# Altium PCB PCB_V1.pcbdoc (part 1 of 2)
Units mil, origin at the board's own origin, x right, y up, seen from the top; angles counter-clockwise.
Board outline 2047.24 x 3937.01 mil, 2 copper layers (Top Layer, Bottom Layer), stack 62.206 mil thick; 59 components, 45 nets, 231 pads, 209 vias.
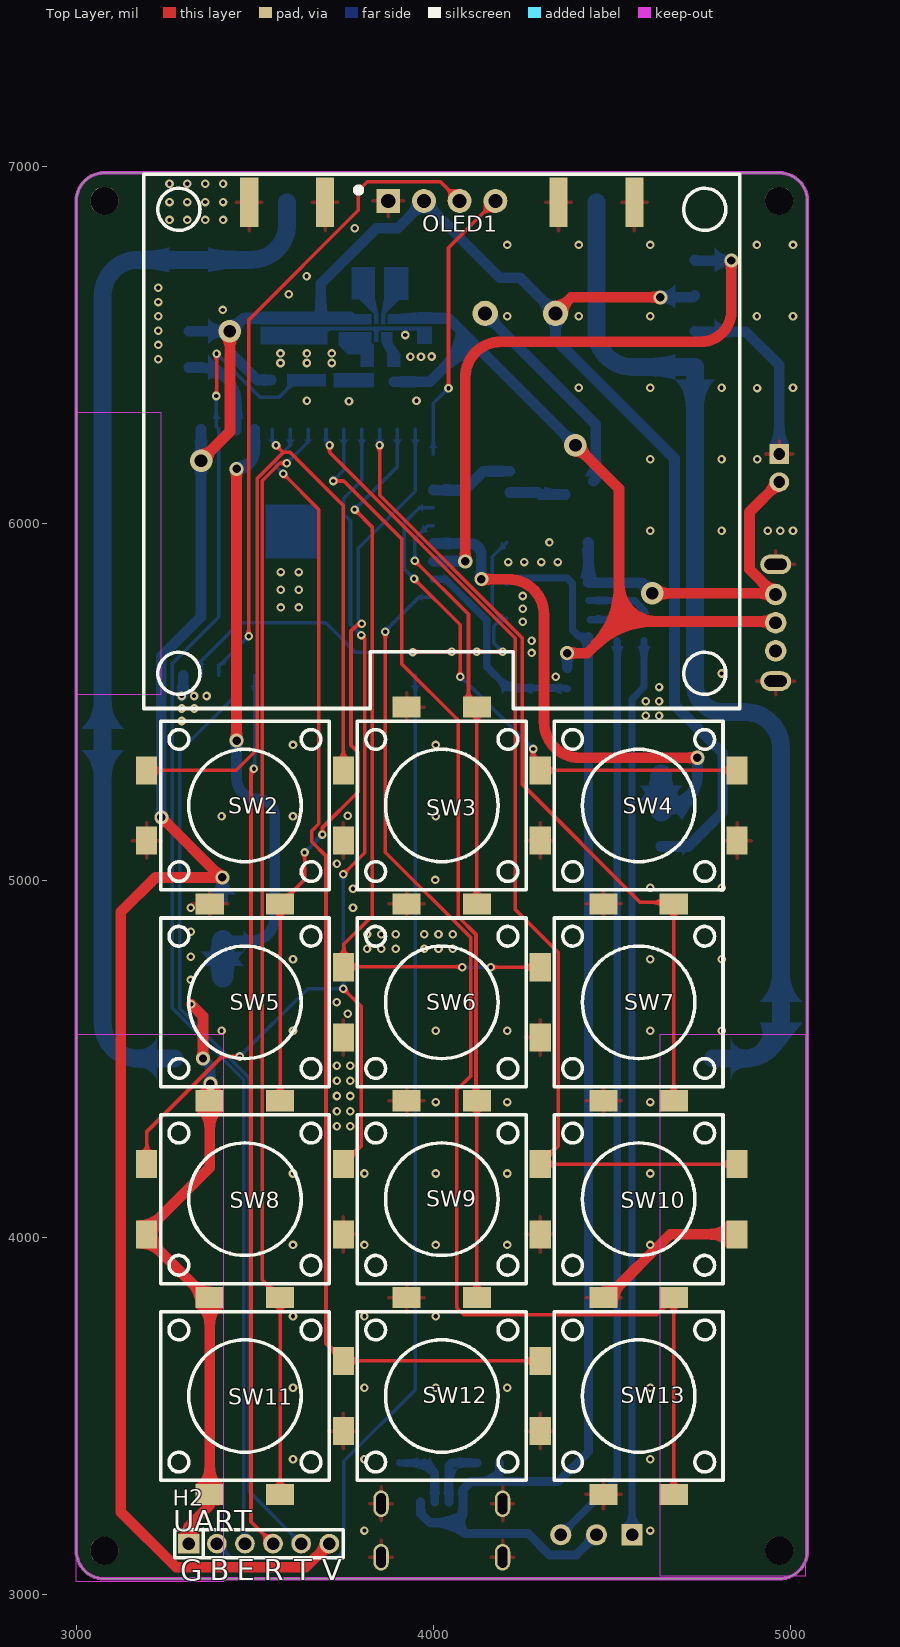
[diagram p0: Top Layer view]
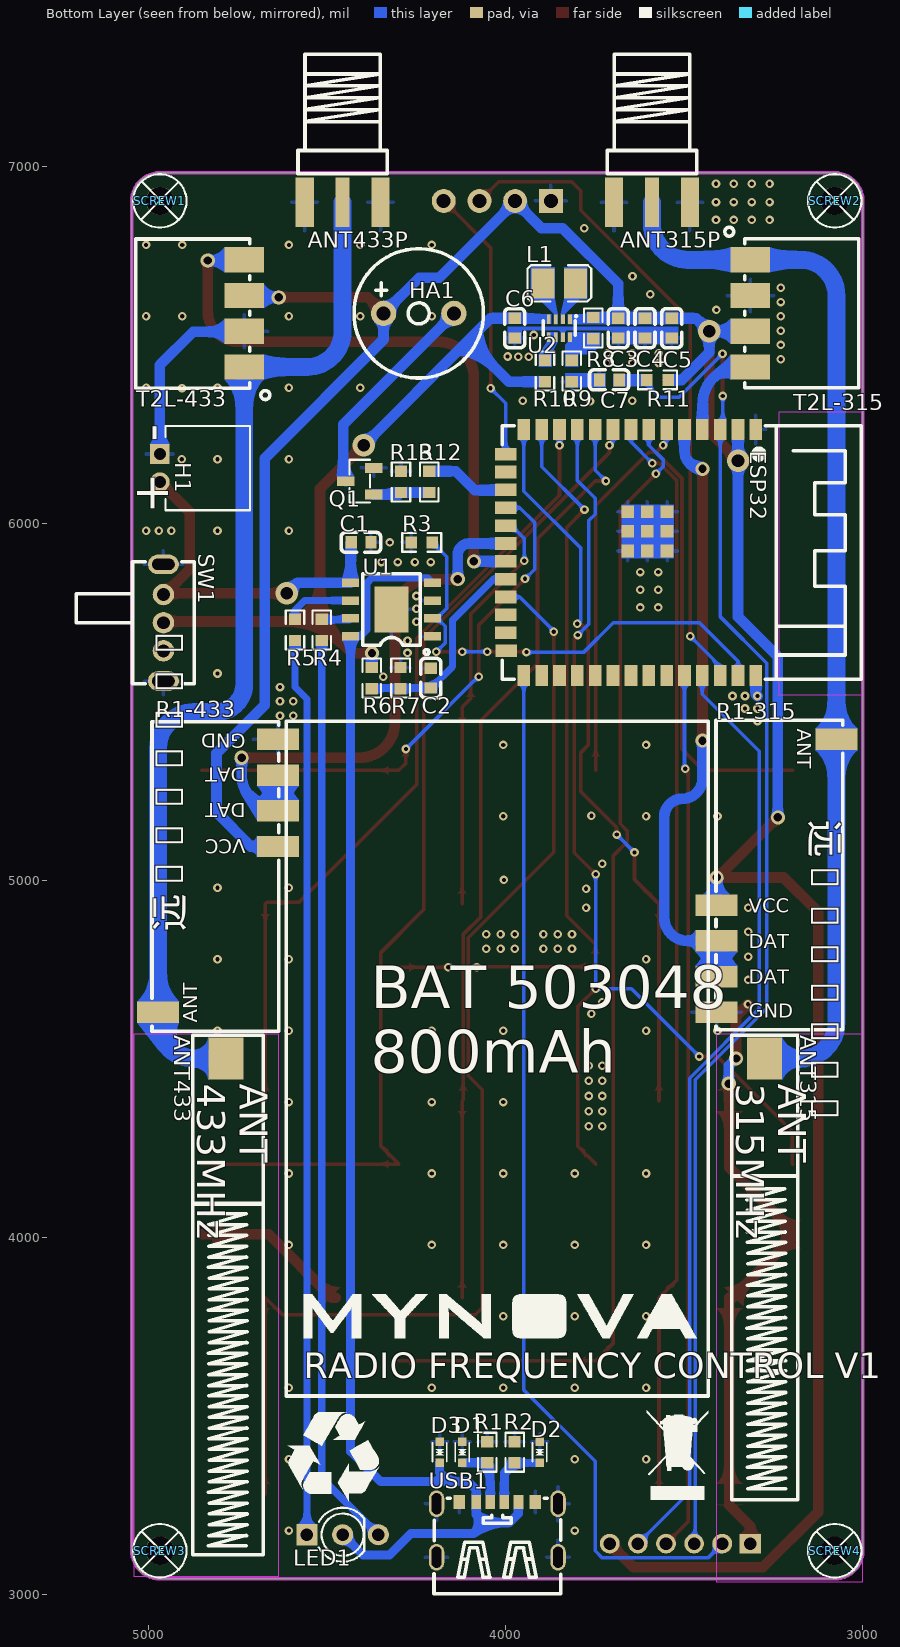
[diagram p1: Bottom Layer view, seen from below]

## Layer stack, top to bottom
Top Solder Mask Layer: solder mask 0.394, Dk 3.3
Top Layer: signal copper 1.379
Dielectric1: surface 59.449, FR4, Dk 4.5
Bottom Layer: signal copper 1.378
Bottom Solder Mask Layer: solder mask 0.394, Dk 3.3

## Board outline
3000,3122.93 ccw(c3078.74,3122.93) 3078.74,3044.19 4968.5,3044.19 ccw(c4968.5,3122.93) 5047.24,3122.93 5047.24,6902.46 ccw(c4968.5,6902.46) 4968.5,6981.2 3078.74,6981.2 ccw(c3078.74,6902.46) 3000,6902.46

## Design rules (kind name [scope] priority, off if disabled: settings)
BoardOutlineClearance copperThickness1oz [All] p0: genericclearance=10 ignorepadtopadclearanceinfootprint=FALSE except(0: Arc-SplitContinuation Track-SplitContinuation SMDPad-SplitContinuation THPad-SplitContinuation Via-SplitContinuation Fill-SplitContinuation Poly-SplitContinuation Region-SplitContinuation Text-SplitContinuation)
BoardOutlineClearance copperThickness2oz [All] p0: genericclearance=10 ignorepadtopadclearanceinfootprint=FALSE except(0: Arc-SplitContinuation Track-SplitContinuation SMDPad-SplitContinuation THPad-SplitContinuation Via-SplitContinuation Fill-SplitContinuation Poly-SplitContinuation Region-SplitContinuation Text-SplitContinuation)
BoardOutlineClearance Plane_innerPlane [All] p0: genericclearance=10 ignorepadtopadclearanceinfootprint=FALSE except(0: Arc-SplitContinuation Track-SplitContinuation SMDPad-SplitContinuation THPad-SplitContinuation Via-SplitContinuation Fill-SplitContinuation Poly-SplitContinuation Region-SplitContinuation Text-SplitContinuation)
BoardOutlineClearance Copper_copperRegion [All] p0: genericclearance=10 ignorepadtopadclearanceinfootprint=FALSE except(0: Arc-SplitContinuation Track-SplitContinuation SMDPad-SplitContinuation THPad-SplitContinuation Via-SplitContinuation Fill-SplitContinuation Poly-SplitContinuation Region-SplitContinuation Text-SplitContinuation)
BoardOutlineClearance Copper_Direct [All] p0: genericclearance=10 ignorepadtopadclearanceinfootprint=FALSE except(0: Arc-SplitContinuation Track-SplitContinuation SMDPad-SplitContinuation THPad-SplitContinuation Via-SplitContinuation Fill-SplitContinuation Poly-SplitContinuation Region-SplitContinuation Text-SplitContinuation)
BoardOutlineClearance otherClearance [All] p0: genericclearance=10 ignorepadtopadclearanceinfootprint=FALSE except(0: Arc-SplitContinuation Track-SplitContinuation SMDPad-SplitContinuation THPad-SplitContinuation Via-SplitContinuation Fill-SplitContinuation Poly-SplitContinuation Region-SplitContinuation Text-SplitContinuation)
Clearance copperThickness1oz [All] p1: gap=7 ignorepadtopadclearanceinfootprint=FALSE
Clearance copperThickness2oz [All] p1: gap=7 ignorepadtopadclearanceinfootprint=FALSE
Clearance Plane_innerPlane [All] p1: gap=7 ignorepadtopadclearanceinfootprint=FALSE
Clearance Copper_copperRegion [All] p1: gap=7 ignorepadtopadclearanceinfootprint=FALSE
Clearance Copper_Direct [All] p1: gap=7 ignorepadtopadclearanceinfootprint=FALSE
Clearance otherClearance [All] p1: gap=7 ignorepadtopadclearanceinfootprint=FALSE
DiffPairsRouting differentialPair [All] p1: maxuncoupledlength=10 minlimit=5.9843 maxlimit=Infinity mostfreqgap=5.9843 toplayer_minwidth=5 toplayer_prefwidth=10 toplayer_maxwidth=100 bottomlayer_minwidth=5 bottomlayer_prefwidth=10 bottomlayer_maxwidth=100
PasteMaskExpansion pasteMaskExpansion [All] p1: expansion=0
PlaneConnect innerPlane [All] p1: planeconnectstyle=Relief reliefexpansion=20 reliefentries=4 reliefconductorwidth=10 reliefairgap=10
PolygonConnect copperRegion [All] p1: connectstyle=Relief reliefentries=4 reliefconductorwidth=10 polygonreliefangle="90 Angle" airgapwidth=10
PolygonConnect Direct [All] p1: connectstyle=Direct reliefentries=4 reliefconductorwidth=10 polygonreliefangle="90 Angle" airgapwidth=10
RoutingVias viaSize [All] p1: viastyle="Through Hole" holewidth=12.0078 minholewidth=11.811 maxholewidth=248.0314 width=12.0078 minwidth=11.811 maxwidth=248.0314
SolderMaskExpansion solderMaskExpansion [All] p1: useseparateexpansions=TRUE expansion=2.0079 expansionbottom=2.0079
Width copperThickness1oz [All] p1: maxlimit=100 minlimit=5 preferedwidth=10
Width copperThickness2oz [All] p1: maxlimit=100 minlimit=8 preferedwidth=10

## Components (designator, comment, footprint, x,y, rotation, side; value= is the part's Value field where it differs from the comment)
ANT315 "" SMD-ANT-315 3275,4500.88 r270 bottom
ANT315P "" SMA-TH_SMA-KE-P901 3590.55,6898.52 r180 bottom
ANT433 "" SMD-ANT-433 4783.46,4500.88 r270 bottom
ANT433P "" SMA-TH_SMA-KE-P901 4456.69,6898.52 r180 bottom
C1 "" C0603 4405,5946.2 r180 bottom
C2 "" C0603 4210,5566.2 r270 bottom
C3 "" C0603 3685,6546.2 r90 bottom
C4 "" C0603 3610,6546.2 r90 bottom
C5 "" C0603 3535,6546.2 r90 bottom
C6 "" C0603 3975,6546.2 r90 bottom
C7 "" C0603 3710,6401.2 r180 bottom
D1 "" SOD-523_L1.2-W0.8-LS1.6-BI 4121.76,3398.52 r90 bottom
D2 "" SOD-523_L1.2-W0.8-LS1.6-BI 3905,3398.52 r90 bottom
D3 "" SOD-523_L1.2-W0.8-LS1.6-BI 4185,3398.52 r90 bottom
ESP32 "" WIRELM-SMD_ESP32-S3-WROOM-1 3649.61,5918.21 r270 bottom
H1 "" CONN-TH_PH-2AW_C2908634 4968.5,6154.43 r270 bottom
H2 "" 6PIN-2MM-UART 3511.81,3142.62 r0 top
HA1 "" BUZ-TH_BD9.0-P5.00-D0.6-FD 4243.58,6587.53 r180 bottom
L1 "" L1008 3850,6671.2 r180 bottom
LED1 "" LED-TH_3P-BD3.8-P2.54-BI 4456.69,3167.62 r180 bottom
OLED1 "" OLED-TH_-4P-L42.4-W38.0-P2.54 4023.62,6902.46 r0 top
Q1 "" SOT-23-3_L2.9-W1.3-P1.90-LS2.4-BR 4408.94,6117.58 r180 bottom
R1 "" R0603 4051.76,3398.52 r90 bottom
R1-315 "" COMM-SMD_YUAN-R1-315 3241.85,5012.69 r270 bottom
R1-433 "" COMM-SMD_YUAN-R1-433 4805.39,5012.69 r90 bottom
R2 "" R0603 3975,3398.52 r90 bottom
R3 "" R0603 4235,5946.2 r180 bottom
R4 "" R0603 4515,5701.2 r90 bottom
R5 "" R0603 4590,5701.2 r90 bottom
R6 "" R0603 4375,5566.2 r90 bottom
R7 "" R0603 4294.47,5566.2 r270 bottom
R8 "" R0603 3755,6546.2 r90 bottom
R9 "" R0603 3815,6426.2 r90 bottom
R10 "" R0603 3890,6426.2 r270 bottom
R11 "" R0603 3575,6401.2 r0 bottom
R12 "" R0603 4214.03,6115.69 r270 bottom
R13 "" R0603 4293.31,6115.69 r90 bottom
SCREW1 "" M2螺丝 4968.5,6902.46 r180 bottom
SCREW2 "" M2螺丝 3078.74,6902.46 r180 bottom
SCREW3 "" M2螺丝 4968.5,3122.93 r180 bottom
SCREW4 "" M2螺丝 3078.74,3122.93 r180 bottom
SW1 "" SW-TH_SK12D07VG4 4958.5,5721.36 r270 bottom
SW2 "" SW-SMD_4P-L12.0-W12.0-P5.00-LS15.4 3472.44,5209.55 r0 top
SW3 "" SW-SMD_4P-L12.0-W12.0-P5.00-LS15.4 4023.62,5209.55 r270 top
SW4 "" SW-SMD_4P-L12.0-W12.0-P5.00-LS15.4 4574.8,5209.55 r0 top
SW5 "" SW-SMD_4P-L12.0-W12.0-P5.00-LS15.4 3472.44,4658.36 r270 top
SW6 "" SW-SMD_4P-L12.0-W12.0-P5.00-LS15.4 4023.62,4658.36 r0 top
SW7 "" SW-SMD_4P-L12.0-W12.0-P5.00-LS15.4 4574.8,4658.36 r270 top
SW8 "" SW-SMD_4P-L12.0-W12.0-P5.00-LS15.4 3472.44,4107.18 r0 top
SW9 "" SW-SMD_4P-L12.0-W12.0-P5.00-LS15.4 4023.62,4107.18 r270 top
SW10 "" SW-SMD_4P-L12.0-W12.0-P5.00-LS15.4 4574.8,4107.18 r0 top
SW11 "" SW-SMD_4P-L12.0-W12.0-P5.00-LS15.4 3472.44,3556 r270 top
SW12 "" SW-SMD_4P-L12.0-W12.0-P5.00-LS15.4 4023.62,3556 r0 top
SW13 "" SW-SMD_4P-L12.0-W12.0-P5.00-LS15.4 4574.8,3556 r270 top
T2L-315 "" WIRELM-SMD_L10.5-W8.3-P2.54 3314.96,6587.5 r270 bottom
T2L-433 "" WIRELM-SMD_L10.5-W8.3-P2.54 4732.28,6587.5 r90 bottom
U1 "" ESOP-8_L4.9-W3.9-P1.27-LS6.0-BL-EP 4319.95,5758.48 r90 bottom
U2 "" SOT-583-8_L2.1-W1.2-P0.50-LS1.6-BL 3850,6546.2 r0 bottom
USB1 "" TYPE-C-SMD_TYPE-C-6P 4023.62,3181.99 r180 bottom

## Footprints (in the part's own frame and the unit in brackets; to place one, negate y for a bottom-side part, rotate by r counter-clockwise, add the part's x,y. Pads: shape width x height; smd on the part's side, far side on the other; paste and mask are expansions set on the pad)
6PIN-2MM-UART [mm]
  round 1.4 hole 0.9: BOOT(-3,0) EN(-1,0) RXD(1,0) TXD(3,0) VCC(5,0)
  rect 1.524x1.4 hole 0.9: GND(-5,0)
  silkscreen extent -6,-1 6,1.02
BUZ-TH_BD9.0-P5.00-D0.6-FD [mm]
  round 1.8 hole 1 copper offset 0,0: 1(-2.5,0)
  round 1.8 hole 1: 2(2.5,0)
  silkscreen extent -4.6,-4.6 4.6,4.6
C0603 [mm]
  rect 0.8x0.9 smd: 1(-0.7,0) 2(0.7,0)
  silkscreen extent -1.41,-0.71 1.39,0.72
COMM-SMD_YUAN-R1-315 [mil]
  rect 60x118.11 smd: 1(82.12,-167.84) 2(182.12,-167.84) 3(282.12,-167.84) 4(382.12,-167.84) 5(-382.12,167.83)
  silkscreen extent -435,-169 431,185
COMM-SMD_YUAN-R1-433 [mil]
  rect 60x118.11 smd: 1(82.12,-167.84) 2(182.12,-167.84) 3(282.12,-167.84) 4(382.12,-167.84) 5(-382.12,167.84)
  silkscreen extent -435,-169 431,185
CONN-TH_PH-2AW_C2908634 [mm]
  rect 1.4x1.4 hole 0.85: 1(-1,0)
  round 1.4 hole 0.85: 2(1,0)
  silkscreen extent -3,0.4 3,6.4
ESOP-8_L4.9-W3.9-P1.27-LS6.0-BL-EP [mm]
  rect 0.6x1.2 smd: 1(-1.905,-2.908) 2(-0.635,-2.908) 3(0.635,-2.908) 4(1.905,-2.908) 5(1.905,2.908) 6(0.635,2.908) 7(-0.635,2.908) 8(-1.905,2.908)
  rect 3.3x2.4 smd: 9(0,0)
  silkscreen extent -3.2,-2.67 2.55,2.05
L1008 [mm]
  rect 1.635x2.16 smd: 1(-1.168,0) 2(1.168,0)
  silkscreen extent -2.27,-1.27 2.27,1.3
LED-TH_3P-BD3.8-P2.54-BI [mm]
  rect 1.5x1.5 hole 0.9: 1(-2.54,0)
  round 1.5 hole 0.9: 2(0,0) 3(2.54,0)
  silkscreen extent -1.7,-1.92 1.54,1.92
M2螺丝 [mm]
  round 2 hole 2: 1(0,0)
  silkscreen extent -1.9,-1.9 1.9,1.9
OLED-TH_-4P-L42.4-W38.0-P2.54 [mm]
  rect 1.7x1.7 hole 1: 1(-3.81,0)
  round 1.7 hole 1: 2(-1.27,0) 3(1.27,0) 4(3.81,0)
  silkscreen extent -21.2,-36.1 21.2,1.91
R0603 [mil]
  rect 31.75x34.02 smd: 1(-29.66,0) 2(29.66,0)
  silkscreen extent -55,-26 55,26
SMA-TH_SMA-KE-P901 [mm]
  rect 1.3x3.5 smd: 1(-2.7,0) 2(2.7,0)
  rect 1.3x3.5 smd far side: 3(-2.7,0) 4(2.7,0)
  rect 1x3.5 smd: 5(0,0)
  silkscreen extent -3.17,2.03 3.18,10.53
SMD-ANT-315 [mm]
  rect 3x2.5 smd: 1(0,0)
  silkscreen extent -1.65,-2.35 31.38,2.35
SMD-ANT-433 [mm]
  rect 3x2.5 smd: 1(0,0)
  silkscreen extent -1.65,-2.35 35.29,2.65
SOD-523_L1.2-W0.8-LS1.6-BI [mm]
  rect 0.6x0.6 smd: 1(-0.75,0) 2(0.75,0)
  silkscreen extent -0.65,-0.5 0.65,0.5
SOT-23-3_L2.9-W1.3-P1.90-LS2.4-BR [mm]
  rect 1.25x0.7 smd: 1(1,-0.95) 2(1,0.95) 3(-1,0)
  silkscreen extent -0.73,-1.53 0.73,1.53
SOT-583-8_L2.1-W1.2-P0.50-LS1.6-BL [mm]
  rect 0.28x0.68 smd: 1(-0.75,-0.64) 2(-0.25,-0.64) 3(0.25,-0.64) 4(0.75,-0.64) 5(0.75,0.64) 6(0.25,0.64) 7(-0.25,0.64) 8(-0.75,0.64)
  silkscreen extent -1.27,-0.93 1.14,0.51
SW-SMD_4P-L12.0-W12.0-P5.00-LS15.4 [mm]
  rect 1.5x2 smd: 1(-7,2.5) 2(7,2.5) 3(-7,-2.5) 4(7,-2.5)
  silkscreen extent -6,-6 6,6
SW-TH_SK12D07VG4 [mil]
  round 60 hole 36: 1(-78.74,0) 2(0,0) 3(78.74,0)
  oval 55.12x86.61 hole 31.5 slot 62.99 at 90 deg: 4(163.38,0) 5(-163.39,0)
  silkscreen extent -171,-244 171,87
TYPE-C-SMD_TYPE-C-6P [mm]
  oval 1.1x1.9 hole 0.7 slot 1.5 at 90 deg: 7(-4.32,-1.963) 7(-4.32,1.838) 7(4.32,-1.963) 7(4.32,1.838)
  rect 0.7x1 smd: A5(-0.5,1.963) A9(1.5,1.963) B5(0.5,1.963) B9(-1.5,1.963)
  rect 0.8x1 smd: A12(2.7,1.963) B12(-2.7,1.963)
  silkscreen extent -4.5,-4.56 4.5,2.24
WIRELM-SMD_ESP32-S3-WROOM-1 [mm]
  rect 1.5x0.9 smd: 1(-8.75,8.895) 2(-8.75,7.625) 3(-8.75,6.355) 4(-8.75,5.085) 5(-8.75,3.815) 6(-8.75,2.545) 7(-8.75,1.275) 8(-8.75,0.005) 9(-8.75,-1.265) 10(-8.75,-2.535) 11(-8.75,-3.805) 12(-8.75,-5.075) 13(-8.75,-6.345) 14(-8.75,-7.615) 27(8.75,-7.615) 28(8.75,-6.345) 29(8.75,-5.075) 30(8.75,-3.805) 31(8.75,-2.535) 32(8.75,-1.265) 33(8.75,0.005) 34(8.75,1.275) 35(8.75,2.545) 36(8.75,3.815) 37(8.75,5.085) 38(8.75,6.355) 39(8.75,7.625) 40(8.75,8.895)
  rect 0.9x1.5 smd: 15(-6.985,-8.895) 16(-5.715,-8.895) 17(-4.445,-8.895) 18(-3.175,-8.895) 19(-1.905,-8.895) 20(-0.635,-8.895) 21(0.635,-8.895) 22(1.905,-8.895) 23(3.175,-8.895) 24(4.445,-8.895) 25(5.715,-8.895) 26(6.985,-8.865)
  rect 0.9x0.9 smd: 41(-2.9,-0.225) 41(-2.9,1.175) 41(-2.9,2.575) 41(-1.5,-0.225) 41(-1.5,1.175) 41(-1.5,2.575) 41(-0.1,-0.225) 41(-0.1,1.175) 41(-0.1,2.575)
  silkscreen extent -9,-9.14 9.02,16.39
WIRELM-SMD_L10.5-W8.3-P2.54 [mm]
  rect 1.8x2.8 smd: 1(-3.81,0) 2(-1.27,0) 3(1.27,0) 4(3.81,0)
  silkscreen extent -6.13,-1.82 5.29,7.7

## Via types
v1: diameter 24.02, hole 12.01, Top Layer to Bottom Layer, 115 vias
v2: diameter 24, hole 12, Top Layer to Bottom Layer, 78 vias
v3: diameter 39.4, hole 23.6, Top Layer to Bottom Layer, 12 vias
v4: diameter 63, hole 35.4, Top Layer to Bottom Layer, 4 vias

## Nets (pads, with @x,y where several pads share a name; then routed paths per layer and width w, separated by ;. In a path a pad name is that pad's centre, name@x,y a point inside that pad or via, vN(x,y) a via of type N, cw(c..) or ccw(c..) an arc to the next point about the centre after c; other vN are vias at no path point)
315_RX: ESP32.5 R1-315.2 R1-315.3 | length 1740.6
  Top Layer w30: v3(3449,5391.2) v3(3449,6152.2)
  Bottom Layer w30: R1-315.2@3409.69,4830.57 3491.37,4830.57 ccw(c3491.37,4895.2) 3556,4895.2 3556,5178.2 ccw(c3506,5178.2) 3506,5228.2 cw(c3506,5285.2) 3449,5285.2 v3(3449,5391.2) ; v3(3449,6152.2) ccw(c3449,6202.61) 3499.41,6202.61 ESP32.5@3499.41,6262.7
  Bottom Layer w60: R1-315.3@3409.69,4730.57 R1-315.2@3409.69,4830.57
315_TX: ESP32.4 T2L-315.4 | length 265.9
  Bottom Layer w30: T2L-315.4@3314.92,6435.93 3348.42,6435.93 cw(c3348.42,6335.93) 3448.42,6335.93 ESP32.4@3448.42,6260.57
315ANT: ANT315.1 ANT315P.5 R1-315.5 T2L-315.1 | length 2986.4
  Bottom Layer w50: ANT315.1@3275,4500.88 3174.02,4500.88 cw(c3174.02,4600.88) 3074.02,4600.88 R1-315.5@3074.02,5394.82 3074.02,6637.5 cw(c3174.02,6637.5) 3174.02,6737.5 T2L-315.1@3314.96,6737.5 3490.55,6737.5 ccw(c3490.55,6837.5) 3590.55,6837.5 ANT315P.5@3590.55,6898.52
433_RX: ESP32.20 R1-433.2 R1-433.3 | length 1547.1
  Top Layer w30: v3(4134.33,5843.2) 4210,5843.2 cw(c4210,5743.2) 4310,5743.2 4310,5443.21 ccw(c4410,5443.21) 4410,5343.21 v3(4739.33,5343.21)
  Bottom Layer w30: ESP32.20@3999.8,5943.21 4102.16,5943.21 cw(c4102.16,5911.04) 4134.33,5911.04 v3(4134.33,5843.2) ; R1-433.2@4637.56,5194.82 4639.33,5194.82 ccw(c4639.33,5294.82) 4739.33,5294.82 v3(4739.33,5343.21)
  Bottom Layer w60: R1-433.2@4637.56,5194.82 R1-433.3@4637.56,5294.82
433_TX: ESP32.21 T2L-433.4 | length 1701.2
  Top Layer w30: v3(4089.33,5893.2) 4089.33,6408.2 cw(c4189.33,6408.2) 4189.33,6508.2 4749,6508.2 ccw(c4749,6593.53) 4834.33,6593.53 v3(4834.33,6735.53)
  Bottom Layer w30: ESP32.21@3999.8,5893.21 v3(4089.33,5893.2) ; T2L-433.4@4732.29,6737.49 ccw(c4734.25,6737.49) 4734.25,6735.53 4735.17,6734.61 4833.41,6734.61 v3(4834.33,6735.53)
433ANT: ANT433.1 ANT433P.5 R1-433.5 T2L-433.1 | length 2941.8
  Bottom Layer w50: ANT433P.5@4456.69,6898.52 4456.69,6537.49 ccw(c4556.69,6537.49) 4556.69,6437.49 T2L-433.1@4732.29,6437.49 4732.29,5548.91 ccw(c4810,5548.91) 4810,5471.2 4873.23,5471.2 cw(c4873.23,5371.2) 4973.23,5371.2 R1-433.5@4973.23,4630.57 4973.23,4600.88 cw(c4873.23,4600.88) 4873.23,4500.88 ANT433.1@4783.46,4500.88
$1N804: 
$1N6847: R4.2 U1.7 | length 74.1
  Bottom Layer w20: U1.7@4438.26,5729.68 R4.2@4512.38,5729.68
$1N7056: LED1.1 R5.1 | length 2517.7
  Bottom Layer w20: LED1.1@4556.69,3167.62 4556.69,5507.89 4590,5541.2 R5.1@4590,5671.54
$1N7064: R5.2 U1.6 | length 192.2
  Bottom Layer w20: U1.6@4434.45,5783.48 4562.72,5783.48 4590,5756.2 R5.2@4590,5730.86
$1N11631: LED1.3 R4.1 | length 2569.5
  Bottom Layer w20: LED1.3@4356.69,3167.62 4515,3325.92 R4.1@4515,5671.54
$1N15750: HA1.2 Q1.3 | length 601.1
  Bottom Layer w30: HA1.2@4145.17,6587.53 4145.16,6586.04 4455,6276.2 4455,6124.27 Q1.3@4448.31,6117.58
$1N15783: Q1.1 R12.2 R13.1 | length 158
  Bottom Layer w30: R12.2@4214.03,6086.03 R13.1@4293.31,6086.03 4299.16,6080.18 Q1.1@4369.57,6080.18
$1N28863: D2.1 R2.1 USB1.B5 | length 191.7
  Bottom Layer w20: D2.1@3905,3369 3905.14,3368.86 R2.1@3975,3368.86
  Bottom Layer w25: R2.1@3975,3368.86 4003.94,3339.92 USB1.B5@4003.94,3259.25
$1N28864: D1.1 R1.1 USB1.A5 | length 183.2
  Bottom Layer w25: USB1.A5@4043.31,3259.25 4043.31,3360.4 R1.1@4051.76,3368.86 4121.63,3368.86 D1.1@4121.76,3369
$1N28916: R10.1 U2.5 U2.6
$1N28917: L1.1 U2.3
$1N28918: L1.2 U2.2
$1N28920: R8.1 R9.2 U2.8
+3.3V: C3.2 C4.2 C5.2 ESP32.2 H2.VCC HA1.1 OLED1.2 R1-315.1 R1-433.1 R8.2 R11.1 T2L-315.3 T2L-433.3 U2.1 | length 8143.5
  Top Layer w30: v3(3238.18,5176.39) v3@3406.4,5008.17 ; v4@3351,6177.2 3430.3,6256.5 v4(3430.3,6537.5) ; v3(3409.41,5008.17) v3@3406.4,5008.17 ; H2.VCC@3708.66,3142.62 3642.24,3076.2 3280,3076.2 3125,3231.2 3125,4911.2 3221.97,5008.17 v3@3406.4,5008.17 ; HA1.1@4342.02,6587.53 4342.01,6588.21 4386.26,6632.46 v3(4635.52,6632.46)
  Bottom Layer w30: v3(3238.18,5176.39) 3238.18,5626.94 3349.41,5738.17 v4(3349.41,6175.38) ESP32.2@3349.41,6262.7 ; T2L-315.3@3314.96,6537.5 v4(3430.3,6537.5) ; R1-315.1@3409.41,4944.35 v3(3409.41,5008.17) ; C5.2@3535,6573.76 3534.56,6574.2 3467,6574.2 v4(3430.3,6537.5) ; R11.1@3545.34,6401.2 3507,6401.2 3430.3,6477.9 v4(3430.3,6537.5) ; C3.2@3685,6573.76 3685,6670.2 3841,6826.2 3900,6826.2 OLED1.2@3973.62,6899.82 ; OLED1.2@3973.63,6902.45 OLED1.2@3973.62,6899.82 ; v3(4635.52,6632.46) 4727.25,6632.46 T2L-433.3@4732.29,6637.49 ; R1-433.1@4637.56,5094.82 4713.62,5094.82 4810,5191.2 4810,5355.69 4675,5490.69 4675,6181.2 4342.01,6514.19 HA1.1@4342.02,6587.53 4242.34,6687.2 4186.24,6687.2 OLED1.2@3973.62,6899.82
ADC: C2.2 ESP32.22 R6.1 R7.2 | length 578.3
  Bottom Layer w20: ESP32.22@3999.8,5843.21 4034.33,5843.2 4149.37,5728.17 4149.37,5598.32 4209.05,5538.64 4372.9,5538.64 R6.1@4375,5536.54
B+: C1.1 H1.2 SW1.1 U1.5 | length 1032.8
  Top Layer w30: v4(4613.08,5803.48) SW1.1@4952.72,5803.48 ; H1.2@4968.5,6115.06 4885,6031.55 4885,5871.2 SW1.1@4952.72,5803.48 ; SW1.1@4952.72,5803.48 4955.12,5803.48 SW1.1@4958.5,5800.1 4956.1,5800.1 SW1.1@4952.72,5803.48
  Bottom Layer w30: C1.1@4432.56,5946.2 4434.45,5944.3 U1.5@4434.45,5833.48 4583.08,5833.48 v4(4613.08,5803.48)
BOOT: ESP32.27 H2.BOOT | length 2914.5
  Bottom Layer w10: H2.BOOT@3393.7,3142.62 3433.7,3102.62 3729.41,3102.62 3749.41,3122.62 3749.41,3373.05 3949.41,3573.05 ESP32.27@3949.41,5573.72
BUZZER: ESP32.17 R12.1 | length 236.7
  Bottom Layer w30: ESP32.17@3999.8,6093.21 4000.81,6092.2 4087,6092.2 4140.15,6145.35 R12.1@4214.03,6145.35
CHG_P: ESP32.39 R3.2 U1.2 | length 1333
  Top Layer w10: v2(3942,5639.2) 3943,5640.2 v2(4052,5640.2) ; v2(4121.38,5640.2) v2(4194.35,5640.2)
  Bottom Layer w10: ESP32.39@3349.41,5573.72 3349.41,5613.24 3457.37,5721.2 3699,5721.2 3782,5638.2 v2@3942,5638.2 ; v2(4052,5640.2) v2(4121.38,5640.2) ; U1.2@4192.72,5733.48 4165.01,5761.19 4165.01,5905.87 R3.2@4205.34,5946.2 ; v2@4194.35,5639.2 4169,5664.55 4169,5711.17 4191.31,5733.48 U1.2@4205.45,5733.48
EN: C7.2 ESP32.3 H2.EN R11.2 | length 3761.6
  Top Layer w10: v2(3392,6356.2) 3393,6357.2 v2(3393,6474.2)
  Bottom Layer w10: v2(3392,6356.2) 3392,6270.11 ESP32.3@3399.41,6262.7 3399.41,5737.49 ; v2(3393,6474.2) 3514,6353.2 3569,6353.2 3604.66,6388.86 R11.2@3604.66,6401.2 ; 3398.72,5737.49 3269.41,5608.17 3269.41,4641.79 3469.41,4441.79 3469.41,3145.65 H2.EN@3472.44,3142.62
GND: ANT315P.1 ANT315P.2 ANT315P.3 ANT315P.4 ANT433P.1 ANT433P.2 ANT433P.3 ANT433P.4 C1.2 C2.1 C3.1 C4.1 C5.1 C6.1 C7.1 D1.2 D2.2 D3.2 ESP32.1 ESP32.40 ESP32.41 H1.1 H2.GND OLED1.1 Q1.2 R1-315.4 R1-433.4 R1.2 R2.2 R3.1 R7.1 R9.1 R13.2 SW1.4 SW1.5 SW2.3 SW2.4 SW3.3 SW3.4 SW4.3 SW4.4 SW5.3 SW5.4 SW6.3 SW6.4 SW7.3 SW7.4 SW8.3 SW8.4 SW9.3 SW9.4 SW10.3 SW10.4 SW11.3 SW11.4 SW12.3 SW12.4 SW13.3 SW13.4 T2L-315.2 T2L-433.2 U1.1 U1.3 U1.9 U2.7 USB1.7 USB1.A12 USB1.B12 | length 2741.1
  Top Layer w30: H2.GND@3314.96,3142.62 3314.96,3191.16 ; 3315,3191.2 3374.02,3250.21 SW11.4@3374.02,3280.41 SW11.3@3374.02,3831.59 3364.17,3831.59 3196.85,3998.92 SW8.3@3196.85,4008.76 3196.85,4018.6 3374.02,4195.77 SW5.4@3374.02,4382.77 3375.42,4384.17 v3(3375.42,4430.78) ; v2(3321.7,4652.9) 3355,4619.59 v3(3355,4501.2) ; SW13.3@4476.38,3831.59 4486.22,3831.59 4663.39,4008.76 SW10.4@4850.39,4008.76
  Bottom Layer w30: v2(3295.26,5516.2) 3299.41,5520.35 ESP32.40@3299.41,5573.72 ; v3(3355,4501.2) 3375.42,4480.78 v3(3375.42,4430.78) ; T2L-433.2@4732.29,6537.49 4733.58,6536.2 4875,6536.2 4968.5,6442.69 H1.1@4968.5,6193.8
  other v1: 3807.01,3179.19 4607.01,3179.19 3607.01,3379.19 3807.01,3379.19 4607.01,3379.19 3607.01,3579.19 3807.01,3579.19 4007.01,3579.19 4207.01,3579.19 4607.01,3579.19 3607.01,3779.19 3807.01,3779.19 4007.01,3779.19 3607.01,3979.19 3807.01,3979.19 4007.01,3979.19 4207.01,3979.19 4607.01,3979.19 3607.01,4179.19 3807.01,4179.19 4007.01,4179.19 4207.01,4179.19 4607.01,4179.19 4007.01,4379.19 4207.01,4379.19 4607.01,4379.19 3407.01,4579.19 3607.01,4579.19 4007.01,4579.19 4207.01,4579.19 4607.01,4579.19 4807.01,4579.19 3607.01,4779.19 4607.01,4779.19 4807.01,4779.19 3814.43,4808.68 3854.43,4808.68 3894.43,4808.68 3974.43,4808.68 4014.43,4808.68 4054.43,4808.68 3814.43,4848.68 3854.43,4848.68 3894.43,4848.68 3974.43,4848.68 4014.43,4848.68 4054.43,4848.68 4607.01,4979.19 4807.01,4979.19 4005,5001.2 3407.01,5179.19 3607.01,5179.19 4007.01,5179.19 3607.01,5379.19 4007.01,5379.19 4807.01,5579.19 4607.01,5979.19 4807.01,5979.19 4936,5979.2 4971,5979.2 5007.01,5979.19 4607.01,6179.19 4807.01,6179.19 4907,6179.2 4906.48,6378.44 4407.01,6379.19 4607.01,6379.19 4807.01,6379.19 5007.01,6379.19 3230.01,6459.19 4207.01,6579.19 4407.01,6579.19 4607.01,6579.19 4906,6579.2 5007.01,6579.19 3410,6597.2 3230.01,6659.19 4207.01,6779.19 4407.01,6779.19 4607.01,6779.19 4906,6779.2 5007.01,6779.19 3261.15,6849.19 3311.15,6849.19 3361.15,6849.19 3411.15,6849.19 3261.15,6899.19 3311.15,6899.19 3361.15,6899.19 3411.15,6899.19 3261.15,6950.41 3311.15,6950.41 3361.15,6950.41 3411.15,6950.41
  other v2: 3730,4311.2 3767.46,4311.2 3730,4353.7 3767.46,4353.7 3730,4396.2 3767.46,4396.2 3730,4438.7 3767.46,4438.7 3730,4481.2 3767.46,4481.2 3760,4626.2 3729.41,4658.36 3320.68,4721.2 3320.68,4786.2 3320.68,4856.2 3320.68,4923.43 3775,4923.59 3775,4976.2 3730,5046.2 3760,5181.2 3295,5446.2 4595,5461.2 4632.02,5461.2 3295,5481.2 3330,5481.2 4595,5501.2 4632.02,5501.2 3330,5516.2 3365,5516.2 4632.02,5541.2 4342.98,5570.12 4275,5636.79 4275,5671.2 4250,5724.2 4250,5760.49 3573,5764.2 3623,5764.2 4250,5796.2 3573,5813.7 3623,5813.7 3573,5863.2 3623,5863.2 4210,5891.2 4254.32,5891.2 4302.16,5891.2 4347.94,5891.2 4325,5946.2 3763.72,6341.36 3645.94,6343 3952.71,6343 3571.86,6448.52 3645.88,6448.52 3715.31,6448.52 3935.73,6466.26 3965.31,6466.26 3994.89,6466.8 3571.95,6475.49 3645.97,6475.49 3715.39,6475.49 3230.02,6499.2 3921.49,6527.06 3230.02,6539.19 3230.02,6579.19 3230.02,6619.19 3595,6641.2 3645,6691.2 3780,6826.2
I2C_SCL: ESP32.38 OLED1.3 | length 1835.5
  Top Layer w10: v1(3483.01,5683.24) 3483.01,6569.21 3790,6876.2 3790,6931.2 3815,6956.2 4019.88,6956.2 OLED1.3@4073.63,6902.45
  Bottom Layer w10: ESP32.38@3399.41,5573.72 3399.41,5599.64 v1(3483.01,5683.24)
I2C_SDA: ESP32.15 OLED1.4 | length 781.2
  Top Layer w10: v2(4042.47,6378.18) 4042.47,6771.31 OLED1.4@4173.63,6902.45
  Bottom Layer w10: ESP32.15@3999.8,6193.21 3999.8,6335.51 v2(4042.47,6378.18)
KEY_1: ESP32.14 SW5.1 SW5.2 | length 2067.4
  Top Layer w10: SW5.2@3570.87,4382.77 SW5.1@3570.87,4933.95 3639.41,5002.5 v1(3639.41,5078.17) ; v1(3689.41,5128.17) 3689.41,5148.17 3789.41,5248.17 3789.41,5358.17 3769.41,5378.17 3769.41,5698.17 3789.41,5718.17 v1(3799.41,5718.17)
  Bottom Layer w10: v1(3639.41,5078.17) v1(3689.41,5128.17) ; v1(3799.41,5718.17) 3789.41,5728.17 3789.41,5929.43 3949.41,6089.43 ESP32.14@3949.41,6262.7
KEY_2: ESP32.13 SW6.1 SW6.2 | length 2160.4
  Top Layer w10: SW6.1@3748.03,4756.79 SW6.1@3749.41,4758.17 ; v1(3779.41,6038.17) 3829.41,5988.17 3829.41,4900.69 3749.41,4820.69 SW6.1@3749.41,4758.17 ; v1(4080.79,4756.79) 4079.41,4758.17 SW6.1@3749.41,4758.17 ; v1(4160.79,4756.79) SW6.2@4299.21,4756.79
  Bottom Layer w10: v1(3779.41,6038.17) 3899.41,6158.17 ESP32.13@3899.41,6262.7 ; v1(4080.79,4756.79) v1(4160.79,4756.79)
KEY_3: ESP32.12 SW7.1 SW7.2 | length 2273.6
  Top Layer w10: v1(3849.41,6218.17) 3849.41,6078.17 4249.41,5678.17 4249.41,5268.17 4579.41,4938.17 4669.01,4938.17 SW7.1@4673.23,4933.95 SW7.2@4673.23,4382.77
  Bottom Layer w10: v1(3849.41,6218.17) ESP32.12@3849.41,6262.7
KEY_4: ESP32.11 SW8.1 SW8.2 | length 2975.7
  Top Layer w10: SW8.1@3196.85,4205.61 3198.03,4206.79 3198.03,4296.79 3408.03,4506.79 v1(3458.03,4506.79) ; SW8.2@3748.03,4205.61 3798.03,4255.61 3798.03,4646.79 v1(3748.03,4696.79) ; v1(3748.03,5016.79) 3808.03,5076.79 3808.03,5676.79 v1(3798.03,5686.79)
  Bottom Layer w10: v1(3458.03,4506.79) 3648.03,4696.79 v1(3748.03,4696.79) v1(3748.03,5016.79) ; v1(3798.03,5686.79) 3768.03,5716.79 3768.03,6006.79 3749.41,6025.41 3749.41,6069.43 3799.41,6119.43 ESP32.11@3799.41,6262.7
KEY_5: ESP32.10 SW9.1 SW9.2 | length 2627.9
  Top Layer w10: v1(3719.41,6118.17) 3749.41,6118.17 3911,5956.58 3911,5606.58 4069.41,5448.17 4069.41,4898.17 4119.41,4848.17 4119.41,4385.41 SW9.1@4122.05,4382.77 SW9.2@4122.05,3831.59
  Bottom Layer w10: v1(3719.41,6118.17) 3749.41,6148.17 ESP32.10@3749.41,6262.7
KEY_6: ESP32.9 SW10.1 SW10.2 | length 2898.3
  Top Layer w10: v1(3709.41,6218.17) 3709.41,6198.17 4229.41,5678.17 4229.41,4918.17 4349.41,4798.17 4349.41,4255.8 SW10.1@4299.21,4205.61 SW10.2@4850.39,4205.61
  Bottom Layer w10: ESP32.9@3699.41,6262.7 3699.41,6228.17 v1(3709.41,6218.17)
KEY_7: ESP32.8 SW11.1 SW11.2 | length 3068.2
  Top Layer w10: SW11.2@3570.87,3280.41 SW11.1@3570.87,3831.59 3520.51,3881.94 3520.51,6119.27 3569.41,6168.17 v1(3589.41,6168.17)
  Bottom Layer w10: v1(3589.41,6168.17) 3649.41,6228.17 ESP32.8@3649.41,6262.7
KEY_8: ESP32.7 SW12.1 SW12.2 | length 3270.7
  Top Layer w10: v1(3579.41,6138.17) 3679.41,6038.17 3679.41,5158.17 3659.41,5138.17 3659.41,5108.17 3699.41,5068.17 3699.41,3703.05 SW12.1@3748.03,3654.43 SW12.2@4299.21,3654.43
  Bottom Layer w10: v1(3579.41,6138.17) 3559.41,6158.17 3559.41,6178.17 3599.41,6218.17 ESP32.7@3599.41,6262.7
KEY_9: ESP32.23 SW13.1 SW13.2 | length 3372.3
  Top Layer w10: v1(3865.27,5696.21) 3865.27,5078.89 4105.27,4838.89 4105.27,4453.21 4065.27,4413.21 4065.27,3803.21 4085.27,3783.21 4624.85,3783.21 SW13.1@4673.23,3831.59 SW13.2@4673.23,3280.41
  Bottom Layer w10: v1(3865.27,5696.21) 3865.27,5698.21 3960.27,5793.21 ESP32.23@3999.8,5793.21
KEY_BACK: ESP32.6 SW2.1 SW2.2 | length 2244.4
  Top Layer w10: SW2.1@3196.85,5307.97 3447.77,5307.97 3506.5,5366.69 3506.5,6125.26 3579.41,6198.17 ; v1(3559.41,6218.17) 3579.41,6198.17 ; SW2.2@3748.03,5307.97 3748.03,6049.55 3599.41,6198.17 3579.41,6198.17
  Bottom Layer w10: ESP32.6@3549.41,6262.7 3549.41,6228.17 v1(3559.41,6218.17)
KEY_ENTER: ESP32.18 SW4.1 SW4.2 | length 1501.7
  Top Layer w10: v2(3946,5844.2) 4074.98,5715.21 4074.98,5570.2 v1(4075.41,5569.78) ; v1(4279.41,5367.78) 4279.41,5327.78 SW4.1@4299.21,5307.97 SW4.2@4850.39,5307.97
  Bottom Layer w10: v2(3946,5844.2) 3919,5871.2 3919,6001.93 3960.27,6043.21 ESP32.18@3999.8,6043.21 ; v1(4075.41,5569.78) 4077.41,5569.78 v1(4279.41,5367.78)
KEY_MENU: ESP32.19 SW3.1 SW3.2 | length 1162.1
  Top Layer w10: v2(3948,5895.2) 4098.4,5744.8 4098.4,5508.78 SW3.1@4122.05,5485.14 SW3.2@4122.05,4933.95
  Bottom Layer w10: v2(3948,5895.2) 3948,5957.2 3984.01,5993.21 ESP32.19@3999.8,5993.21
RXD: ESP32.36 H2.RXD | length 2460.8
  Top Layer w10: v1(3497.52,5312.19) 3489.41,5304.08 3489.41,3204.39 H2.RXD@3551.18,3142.62
  Bottom Layer w10: v1(3497.52,5312.19) 3499.41,5314.08 ESP32.36@3499.41,5573.72
TXD: ESP32.37 H2.TXD | length 2638.4
  Bottom Layer w10: ESP32.37@3449.41,5573.72 3450,5573.13 3450,5521.2 3290,5361.2 3290,4641.2 3485,4446.2 3485,3287.54 H2.TXD@3629.92,3142.62
VBUS: D3.1 LED1.2 U1.4 U1.8 USB1.A9 USB1.B9 | length 3818.1
  Bottom Layer w20: U1.4@4205.45,5833.48 4218.17,5846.2 4375,5846.2 4389.14,5832.06 4389.14,5701.62 4407.28,5683.48 U1.8@4434.45,5683.48
  Bottom Layer w25: USB1.A9@3964.57,3259.25 3964.57,3226.63 3990,3201.2 4059.98,3201.2 ; D3.1@4185,3369 4185,3341.2 4160,3316.2 ; U1.8@4434.45,5683.48 4434.45,3400.65 4350,3316.2 4160,3316.2 ; LED1.2@4456.69,3167.62 4400.28,3111.2 4325,3111.2 4265,3171.2 4089.98,3171.2 4059.98,3201.2 ; 4059.98,3201.2 4082.68,3223.89 USB1.B9@4082.68,3259.25 4082.68,3293.88 4105,3316.2 4160,3316.2
VCC: C6.2 R6.2 R10.2 SW1.2 U2.4 | length 2041.1
  Top Layer w30: v3(4374.47,5636.24) 4431.19,5636.24 4520,5725.05 ; v4(4397.83,6218.33) 4520,6096.15 4520,5725.05 ; SW1.2@4958.5,5721.36 4954.81,5725.05 4520,5725.05
  Bottom Layer w30: R10.2@3889.43,6395.94 3990.54,6395.94 4105.38,6510.78 ; C6.2@3975,6573.76 4042.4,6573.76 4105.38,6510.78 ; 4105.85,6511.26 4105.38,6510.78 ; v3(4374.47,5636.24) 4375,5635.71 R6.2@4375,5595.86 ; v4(4397.83,6218.33) 4105.38,6510.78
pads on no net: ESP32.16 ESP32.24 ESP32.25 ESP32.26 ESP32.28 ESP32.29 ESP32.30 ESP32.31 ESP32.32 ESP32.33 ESP32.34 ESP32.35 SCREW1.1 SCREW2.1 SCREW3.1 SCREW4.1 SW1.3

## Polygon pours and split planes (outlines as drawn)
GND on Top Layer (solid, remove dead copper, pour order 0): 3000,6981.2 5047.24,6981.2 5047.24,3044.19 3000,3044.19
GND on Bottom Layer (solid, remove dead copper, pour order 2): 3000,6981.2 5047.24,6981.2 5047.24,3044.19 3000,3044.19

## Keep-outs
Board Outline Layer:
  region: 4635,4568.4 5041.18,4568.4 5041.18,3051.2 4635,3051.2
  region: 3000,4568.4 3411.18,4568.4 3411.18,3036.2 3000,3036.2
  region: 3000,6311.2 3236.18,6311.2 3236.18,5519.92 3000,5519.92
  lines w10: 3000,3122.93 ccw(c3078.74,3122.93) 3078.74,3044.19 4968.5,3044.19 ccw(c4968.5,3122.93) 5047.24,3122.93 5047.24,6902.46 ccw(c4968.5,6902.46) 4968.5,6981.2 3078.74,6981.2 ccw(c3078.74,6902.46) 3000,6902.46 3000,3122.93

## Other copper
Top Layer:
  region net B+: 4915.25,5788.48 4920.33,5818.48 4923.49,5818.64 4926.65,5819.1 4929.71,5819.78 4932.63,5820.65 4935.32,5821.62 4937.71,5822.66 4939.74,5823.7 4941.33,5824.69 4936.25,5779.98 4934.82,5781.31 4932.87,5782.72 4930.48,5784.15 4927.76,5785.49 4924.78,5786.68 4921.65,5787.62 4918.44,5788.25
  region net B+: 4918.74,5816.25 4938.15,5839.26 4940.55,5837.16 4943.23,5835.33 4946.07,5833.76 4948.96,5832.46 4951.78,5831.44 4954.41,5830.7 4956.76,5830.25 4958.68,5830.1 4928.72,5796.53 4928.38,5798.39 4927.77,5800.62 4926.9,5803.13 4925.76,5805.8 4924.37,5808.55 4922.73,5811.28 4920.85,5813.87
  region net VCC: 4915.04,5710.05 4920.58,5740.05 4923.75,5740.21 4926.9,5740.65 4929.96,5741.32 4932.88,5742.16 4935.56,5743.12 4937.96,5744.14 4939.99,5745.16 4941.58,5746.13 4936.04,5701.47 4934.62,5702.81 4932.67,5704.24 4930.29,5705.68 4927.57,5707.03 4924.59,5708.23 4921.44,5709.18 4918.23,5709.82
  region net +3.3V: 3692.74,3105.48 3671.52,3126.69 3673.49,3128.85 3675.3,3131.19 3676.9,3133.62 3678.29,3136.06 3679.44,3138.43 3680.31,3140.66 3680.89,3142.66 3681.16,3144.34 3710.39,3115.11 3708.7,3114.85 3706.7,3114.27 3704.48,3113.39 3702.1,3112.25 3699.66,3110.86 3697.23,3109.25 3694.9,3107.45
  region net RXD: 3521.11,3165.61 3528.18,3172.68 3529.31,3171.76 3530.61,3171.02 3532.07,3170.45 3533.65,3170.02 3537.1,3169.56 3540.73,3169.47 3544.34,3169.63 3547.72,3169.89 3550.64,3170.1 3552.91,3170.12 3523.68,3140.89 3523.7,3143.15 3523.91,3146.08 3524.17,3149.45 3524.32,3153.06 3524.24,3156.7 3523.77,3160.14 3523.35,3161.73 3522.78,3163.18 3522.04,3164.49
  region net GND: 3299.96,3191.16 3329.96,3191.16 ccw(c3352.14,3191.16) 3344.96,3170.18 3284.96,3170.18 ccw(c3277.78,3191.16)
  region net I2C_SCL: 4037.87,6931.13 4044.94,6938.2 4046.31,6937.09 4047.91,6936.22 4049.71,6935.56 4051.68,6935.1 4053.77,6934.8 4055.97,6934.65 4060.5,6934.69 4065.02,6935.02 4069.24,6935.45 4072.9,6935.79 4075.72,6935.85 4040.22,6900.36 4040.28,6903.18 4040.62,6906.83 4041.05,6911.06 4041.39,6915.57 4041.42,6920.11 4041.27,6922.3 4040.98,6924.4 4040.51,6926.36 4039.86,6928.16 4038.98,6929.76
  region net I2C_SDA: 4144.94,6866.7 4137.87,6873.77 4138.98,6875.14 4139.86,6876.75 4140.51,6878.55 4140.98,6880.51 4141.27,6882.61 4141.42,6884.8 4141.39,6889.34 4141.06,6893.85 4140.62,6898.07 4140.28,6901.73 4140.22,6904.55 4175.72,6869.05 4172.9,6869.11 4169.24,6869.46 4165.02,6869.89 4160.5,6870.22 4155.97,6870.26 4153.77,6870.11 4151.68,6869.81 4149.71,6869.35 4147.91,6868.69 4146.31,6867.82
  region net +3.3V: 4364.92,6632.33 4386.64,6611.62 4385.38,6610.24 4384.24,6608.72 4382.27,6605.4 4380.7,6601.81 4379.49,6598.13 4378.59,6594.52 4377.97,6591.15 4377.58,6588.18 4377.4,6585.79 4339.31,6622.86 4344.62,6623.53 4347.95,6624.19 4351.52,6625.12 4355.17,6626.36 4358.72,6627.95 4362.03,6629.92 4363.53,6631.07
  region net B+: 4952.58,6077.92 4931.37,6099.13 4933.34,6101.29 4935.14,6103.63 4936.75,6106.06 4938.13,6108.5 4939.28,6110.87 4940.15,6113.1 4940.74,6115.1 4941,6116.78 4970.23,6087.55 4968.54,6087.29 4966.54,6086.71 4964.32,6085.83 4961.94,6084.69 4959.5,6083.3 4957.07,6081.69 4954.74,6079.89
  region net KEY_BACK: 3241.38,5312.97 3241.38,5302.97 ccw(c3241.38,5284.22) 3226.38,5295.47 3226.38,5320.47 ccw(c3241.38,5331.72)
  region net KEY_BACK: 3743.03,5362.34 3753.03,5362.34 ccw(c3771.78,5362.34) 3760.53,5347.34 3735.53,5347.34 ccw(c3724.28,5362.34)
  region net KEY_MENU: 4093.4,5529.66 4103.4,5529.66 ccw(c4122.15,5529.66) 4110.9,5514.66 4085.9,5514.66 ccw(c4074.65,5529.66)
  region net KEY_MENU: 4127.05,5440.61 4117.05,5440.61 ccw(c4098.3,5440.61) 4109.55,5455.61 4134.55,5455.61 ccw(c4145.8,5440.61)
  region net KEY_MENU: 4117.05,4978.48 4127.05,4978.48 ccw(c4145.8,4978.48) 4134.55,4963.48 4109.55,4963.48 ccw(c4098.3,4978.48)
  region net KEY_ENTER: 4274.41,5362.34 4284.41,5362.34 ccw(c4303.16,5362.34) 4291.91,5347.34 4269.69,5347.34 ccw(c4248.22,5362.34)
  region net KEY_ENTER: 4343.74,5312.97 4343.74,5302.97 ccw(c4343.74,5284.22) 4328.74,5295.47 4328.74,5320.47 ccw(c4343.74,5331.72)
  region net KEY_ENTER: 4805.87,5302.97 4805.87,5312.97 ccw(c4805.87,5331.72) 4820.87,5320.47 4820.87,5295.47 ccw(c4805.87,5284.22)
  region net KEY_1: 3575.86,4889.43 3565.86,4889.43 ccw(c3547.11,4889.43) 3558.36,4904.43 3583.36,4904.43 ccw(c3594.61,4889.43)
  region net KEY_1: 3601.21,4971.37 3619.46,4975.48 ccw(c3660.72,4934.21) 3610.24,4963.48 3587.89,4963.48 ccw(c3579.13,4993.45)
  region net KEY_1: 3565.86,4427.3 3575.86,4427.3 ccw(c3594.61,4427.3) 3583.36,4412.3 3558.36,4412.3 ccw(c3547.11,4427.3)
  region net GND: 3389.02,4308.25 3359.02,4308.25 ccw(c3302.77,4308.25) 3336.52,4353.25 3411.52,4353.25 ccw(c3445.27,4308.25)
  region net GND: 3360.42,4430.78 3390.42,4430.78 ccw(c3412.92,4435.24) 3412.92,4412.3 3337.92,4412.3 ccw(c3337.92,4435.24)
  region net KEY_2: 3792.56,4763.17 3792.56,4753.17 ccw(c3792.56,4734.42) 3777.56,4745.67 3777.56,4770.67 ccw(c3792.56,4781.92)
  region net KEY_2: 3744.41,4811.16 3754.41,4811.16 ccw(c3773.16,4811.16) 3761.91,4796.16 3736.91,4796.16 ccw(c3725.66,4811.16)
  region net KEY_2: 4254.69,4751.79 4254.69,4761.79 ccw(c4254.69,4780.54) 4269.69,4769.29 4269.69,4744.29 ccw(c4254.69,4733.04)
  region net KEY_3: 4618.86,4933.17 4618.86,4943.17 ccw(c4618.86,4961.92) 4633.86,4950.67 4633.86,4925.67 ccw(c4618.86,4914.42)
  region net KEY_3: 4678.23,4889.43 4668.23,4889.43 ccw(c4649.48,4889.43) 4660.73,4904.43 4685.73,4904.43 ccw(c4696.98,4889.43)
  region net KEY_3: 4668.23,4427.3 4678.23,4427.3 ccw(c4696.98,4427.3) 4685.73,4412.3 4660.73,4412.3 ccw(c4649.48,4427.3)
  region net KEY_4: 3193.03,4259.98 3203.03,4259.98 ccw(c3221.78,4259.98) 3210.53,4244.98 3185.53,4244.98 ccw(c3174.28,4259.98)
  region net KEY_4: 3789.55,4254.2 3785.45,4235.96 ccw(c3807.53,4213.88) 3777.56,4222.64 3777.56,4244.98 ccw(c3748.22,4295.53)
  region net GND: 3242.29,3974.69 3221.07,3953.48 ccw(c3173.34,3889.84) 3173.34,3969.39 3226.38,4022.42 ccw(c3305.93,4022.42)
  region net GND: 3221.07,4064.04 3242.29,4042.82 ccw(c3305.93,3995.09) 3226.38,3995.09 3173.34,4048.13 ccw(c3173.34,4127.68)
  region net KEY_5: 4127.05,4338.25 4117.05,4338.25 ccw(c4098.3,4338.25) 4109.55,4353.25 4134.55,4353.25 ccw(c4145.8,4338.25)
  region net KEY_5: 4114.41,4427.3 4124.41,4427.3 ccw(c4143.16,4427.3) 4131.91,4412.3 4106.91,4412.3 ccw(c4095.66,4427.3)
  region net KEY_5: 4117.05,3876.12 4127.05,3876.12 ccw(c4145.8,3876.12) 4134.55,3861.12 4109.55,3861.12 ccw(c4098.3,3876.12)
  region net KEY_6: 4340.73,4254.2 4336.63,4235.96 ccw(c4358.71,4213.88) 4328.74,4222.64 4328.74,4244.98 ccw(c4299.45,4295.49)
  region net KEY_6: 4343.74,4210.61 4343.74,4200.61 ccw(c4343.74,4181.86) 4328.74,4193.11 4328.74,4218.11 ccw(c4343.74,4229.36)
  region net KEY_6: 4805.87,4200.61 4805.87,4210.61 ccw(c4805.87,4229.36) 4820.87,4218.11 4820.87,4193.11 ccw(c4805.87,4181.86)
  region net GND: 4775.87,3993.76 4775.87,4023.76 ccw(c4775.87,4080.01) 4820.87,4046.26 4820.87,3971.26 ccw(c4775.87,3937.51)
  region net KEY_7: 3575.86,3787.06 3565.86,3787.06 ccw(c3547.11,3787.06) 3558.36,3802.06 3583.36,3802.06 ccw(c3594.61,3787.06)
  region net KEY_7: 3522.27,3873.11 3540.51,3869.01 ccw(c3562.59,3891.09) 3553.84,3861.12 3531.5,3861.12 ccw(c3480.95,3831.79)
  region net KEY_7: 3565.86,3324.94 3575.86,3324.94 ccw(c3594.61,3324.94) 3583.36,3309.94 3558.36,3309.94 ccw(c3547.11,3324.94)
  region net GND: 3318.74,3855.82 3339.95,3877.03 ccw(c3387.68,3940.67) 3387.68,3861.12 3334.65,3808.09 ccw(c3255.1,3808.09)
  region net GND: 3389.02,3757.06 3359.02,3757.06 ccw(c3302.77,3757.06) 3336.52,3802.06 3411.52,3802.06 ccw(c3445.27,3757.06)
  region net GND: 3389.02,3250.21 3359.02,3250.21 ccw(c3336.51,2872.33) 3336.52,3250.88 3411.52,3250.88 ccw(c3411.52,2872.33)
  region net GND: 3359.02,3354.94 3389.02,3354.94 ccw(c3445.27,3354.94) 3411.52,3309.94 3336.52,3309.94 ccw(c3302.77,3354.94)
  region net KEY_8: 3710.61,3684.78 3706.51,3703.02 ccw(c3747.82,3744.32) 3718.5,3693.8 3718.5,3671.46 ccw(c3688.53,3662.7)
  region net KEY_8: 3792.56,3659.43 3792.56,3649.43 ccw(c3792.56,3630.68) 3777.56,3641.93 3777.56,3666.93 ccw(c3792.56,3678.18)
  region net KEY_8: 4254.69,3649.43 4254.69,3659.43 ccw(c4254.69,3678.18) 4269.69,3666.93 4269.69,3641.93 ccw(c4254.69,3630.68)
  region net KEY_9: 4642.88,3794.17 4624.64,3790.07 ccw(c4583.38,3831.32) 4633.86,3802.06 4656.2,3802.06 ccw(c4664.96,3772.09)
  region net KEY_9: 4678.23,3787.06 4668.23,3787.06 ccw(c4649.48,3787.06) 4660.73,3802.06 4685.73,3802.06 ccw(c4696.98,3787.06)
  region net KEY_9: 4668.23,3324.94 4678.23,3324.94 ccw(c4696.98,3324.94) 4685.73,3309.94 4660.73,3309.94 ccw(c4649.48,3324.94)
  region net GND: 4510.44,3877.03 4531.66,3855.82 ccw(c4595.3,3808.09) 4515.75,3808.09 4462.72,3861.12 ccw(c4462.72,3940.67)
  region net RXD: 3494.41,5291.81 3484.41,5304.01 3484.58,5306.5 3484.95,5308.84 3485.33,5310.86 3485.51,5312.41 3498.46,5300.22 3497.7,5299.97 3496.97,5299.4 3496.29,5298.55 3495.67,5297.47 3495.16,5296.21 3494.76,5294.81 3494.5,5293.33
  region net KEY_BACK: 3574.5,6210.14 3567.43,6203.07 3565.91,6204.11 3563.67,6205.07 3561.11,6205.81 3558.66,6206.18 3571.39,6218.92 3571.77,6216.47 3572.51,6213.91 3573.47,6211.67
  region net KEY_ENTER: 4069.98,5585.8 4079.98,5586.44 4080.34,5584.58 4081.28,5582.3 4082.61,5579.98 4084.13,5578.03 4066.13,5577.4 4067.54,5579.44 4068.78,5581.78 4069.65,5584.04
  region net KEY_ENTER: 4284.41,5351.43 4274.41,5351.43 4274.06,5353.24 4273.16,5355.5 4271.87,5357.83 4270.4,5359.83 4288.41,5359.83 4286.94,5357.83 4285.66,5355.5 4284.75,5353.24
  region net KEY_1: 3783.63,5705.32 3784.14,5719.97 3787.65,5723.31 3790.17,5725.83 3792.45,5708.39 3791.7,5708.71 3790.75,5708.8 3789.64,5708.66 3788.43,5708.32 3787.18,5707.8 3785.92,5707.12 3784.72,5706.28
  region net KEY_1: 3684.41,5144.52 3694.41,5144.52 3694.76,5142.71 3695.66,5140.44 3696.95,5138.11 3698.42,5136.11 3680.41,5136.11 3681.88,5138.11 3683.16,5140.44 3684.07,5142.71
  region net KEY_1: 3644.41,5061.82 3634.41,5061.82 3634.07,5063.63 3633.16,5065.9 3631.88,5068.23 3630.41,5070.23 3648.42,5070.23 3646.95,5068.23 3645.66,5065.9 3644.76,5063.63
  region net KEY_2: 3794.51,6030.14 3787.44,6023.07 3785.91,6024.11 3783.67,6025.07 3781.11,6025.81 3778.66,6026.18 3791.4,6038.92 3791.77,6036.47 3792.51,6033.91 3793.47,6031.67
  region net KEY_2: 4063.46,4753.17 4065.53,4763.17 4067.21,4763.47 4069.44,4764.26 4071.81,4765.37 4073.94,4766.65 4071.87,4748.76 4070.03,4750.38 4067.75,4751.79 4065.43,4752.79 4064.38,4753.07
  region net KEY_2: 4177.14,4761.79 4177.14,4751.79 4175.33,4751.45 4173.07,4750.54 4170.74,4749.25 4168.74,4747.78 4168.74,4765.8 4170.74,4764.32 4173.07,4763.04 4175.33,4762.13
  region net KEY_3: 3854.41,6201.82 3844.41,6201.82 3844.07,6203.63 3843.16,6205.9 3841.88,6208.23 3840.41,6210.23 3858.42,6210.23 3856.95,6208.23 3855.66,6205.9 3854.76,6203.63
  region net KEY_4: 3811.57,5680.32 3804.49,5673.25 3803.54,5673.72 3801.8,5674.18 3799.6,5674.56 3797.28,5674.8 3810.01,5687.54 3810.25,5685.22 3810.64,5683.02 3811.1,5681.27
  region net KEY_4: 3756.05,5031.88 3763.13,5024.81 3762.09,5023.29 3761.13,5021.05 3760.39,5018.49 3760.01,5016.04 3747.28,5028.77 3749.73,5029.15 3752.29,5029.89 3754.53,5030.85
  region net KEY_4: 3763.13,4688.77 3756.05,4681.69 3754.53,4682.73 3752.29,4683.69 3749.73,4684.43 3747.28,4684.81 3760.01,4697.54 3760.39,4695.09 3761.13,4692.53 3762.09,4690.29
  region net KEY_4: 3441.68,4501.79 3441.68,4511.79 3443.49,4512.13 3445.76,4513.04 3448.09,4514.33 3450.09,4515.8 3450.09,4497.78 3448.09,4499.26 3445.76,4500.54 3443.49,4501.45
  region net KEY_5: 3735.76,6123.17 3735.76,6113.17 3733.95,6112.82 3731.68,6111.92 3729.35,6110.63 3727.35,6109.16 3727.35,6127.17 3729.35,6125.7 3731.68,6124.42 3733.95,6123.51
  region net KEY_6: 3714.41,6201.82 3704.41,6201.82 3704.06,6203.63 3703.16,6205.9 3701.87,6208.23 3700.4,6210.23 3718.41,6210.23 3716.94,6208.23 3715.66,6205.9 3714.75,6203.63
  region net KEY_7: 3573.06,6163.17 3573.06,6173.17 3574.87,6173.51 3577.14,6174.42 3579.47,6175.7 3581.47,6177.17 3581.47,6159.16 3579.47,6160.63 3577.14,6161.92 3574.87,6162.82
  region net KEY_8: 3594.5,6130.14 3587.43,6123.07 3585.91,6124.11 3583.67,6125.07 3581.11,6125.81 3578.66,6126.18 3591.39,6138.92 3591.77,6136.47 3592.51,6133.91 3593.47,6131.67
  region net KEY_9: 3870.27,5679.86 3860.27,5679.86 3859.93,5681.67 3859.02,5683.93 3857.74,5686.26 3856.27,5688.26 3874.28,5688.26 3872.81,5686.26 3871.53,5683.93 3870.62,5681.67
  region net I2C_SCL: 3478.01,5699.59 3488.01,5699.59 3488.35,5697.78 3489.26,5695.51 3490.54,5693.18 3492.01,5691.18 3474,5691.18 3475.47,5693.18 3476.76,5695.51 3477.66,5697.78
  region net B+: 4655.96,5818.48 4655.96,5788.48 4652.63,5788.24 4649.29,5787.57 4646.04,5786.58 4642.96,5785.34 4640.12,5783.96 4637.61,5782.52 4635.52,5781.13 4633.91,5779.86 4633.91,5827.11 4635.52,5825.84 4637.61,5824.44 4640.12,5823 4642.96,5821.62 4646.04,5820.38 4649.29,5819.39 4652.63,5818.72
  region net VCC: 4438.76,6198.61 4417.55,6177.4 4415.02,6179.58 4412.19,6181.47 4409.19,6183.06 4406.13,6184.37 4403.15,6185.4 4400.36,6186.16 4397.89,6186.65 4395.86,6186.89 4429.27,6220.3 4429.5,6218.27 4430,6215.79 4430.76,6213 4431.79,6210.02 4433.09,6206.97 4434.69,6203.96 4436.57,6201.14
  region net VCC: 4398.11,5651.24 4398.11,5621.24 4394.58,5621.04 4391.11,5620.51 4387.75,5619.75 4384.55,5618.89 4378.87,5617.28 4376.48,5616.74 4374.47,5616.54 4374.47,5655.94 4376.48,5655.74 4378.87,5655.21 4384.55,5653.59 4387.75,5652.73 4391.11,5651.98 4394.58,5651.44
  region net +3.3V: 4611.88,6617.46 4611.88,6647.46 4615.41,6647.66 4618.88,6648.19 4622.24,6648.94 4625.44,6649.81 4631.12,6651.42 4633.51,6651.95 4635.52,6652.16 4635.52,6612.76 4633.51,6612.96 4631.12,6613.49 4625.44,6615.11 4622.24,6615.97 4618.88,6616.72 4615.41,6617.25
  region net 433_TX: 4849.33,6711.89 4819.33,6711.89 4819.13,6715.42 4818.59,6718.89 4817.84,6722.25 4816.98,6725.44 4815.36,6731.13 4814.83,6733.51 4814.63,6735.53 4854.03,6735.53 4853.83,6733.51 4853.29,6731.13 4851.68,6725.44 4850.81,6722.25 4850.06,6718.89 4849.53,6715.42
  region net 433_TX: 4074.33,5916.84 4104.33,5916.84 4104.53,5913.31 4105.06,5909.84 4105.82,5906.48 4106.68,5903.29 4108.29,5897.6 4108.83,5895.22 4109.03,5893.2 4069.63,5893.2 4069.83,5895.22 4070.36,5897.6 4071.98,5903.29 4072.84,5906.48 4073.59,5909.84 4074.13,5913.31
  region net 433_RX: 4157.97,5858.2 4157.97,5828.2 4154.44,5828 4150.96,5827.47 4147.6,5826.72 4144.41,5825.85 4138.73,5824.24 4136.34,5823.71 4134.33,5823.5 4134.33,5862.9 4136.34,5862.7 4138.73,5862.17 4144.41,5860.55 4147.6,5859.69 4150.96,5858.94 4154.44,5858.41
  region net 433_RX: 4715.69,5328.21 4715.69,5358.21 4719.22,5358.41 4722.69,5358.94 4726.05,5359.69 4729.25,5360.56 4734.93,5362.17 4737.32,5362.7 4739.33,5362.91 4739.33,5323.51 4737.32,5323.71 4734.93,5324.24 4729.25,5325.86 4726.05,5326.72 4722.69,5327.47 4719.22,5328
  region net +3.3V: 3385.77,4993.17 3385.77,5023.17 3389.3,5023.37 3392.77,5023.91 3396.13,5024.66 3399.33,5025.52 3405.01,5027.14 3407.4,5027.67 3409.41,5027.87 3409.41,4988.47 3407.4,4988.67 3405.01,4989.21 3399.33,4990.82 3396.13,4991.68 3392.77,4992.44 3389.3,4992.97
  region net +3.3V: 3382.09,5011.27 3399.91,5035.87 3402.59,5033.56 3405.53,5031.59 3408.59,5029.92 3411.66,5028.47 3417.27,5026.05 3419.55,5024.95 3421.32,5023.86 3397.06,4992.82 3395.63,4994.19 3394.1,4996.02 3390.69,5000.65 3386.73,5005.99 3384.5,5008.68
  region net +3.3V: 3265.5,5170.28 3244.29,5149.07 3241.65,5151.43 3238.82,5153.5 3235.91,5155.35 3233.04,5157 3227.88,5159.87 3225.81,5161.18 3224.25,5162.46 3252.11,5190.32 3253.39,5188.76 3254.7,5186.69 3257.58,5181.53 3259.22,5178.66 3261.07,5175.76 3263.15,5172.92
  region net GND: 3390.42,4407.14 3360.42,4407.14 3360.21,4410.68 3359.68,4414.15 3358.93,4417.51 3358.07,4420.7 3356.45,4426.38 3355.92,4428.77 3355.72,4430.78 3395.12,4430.78 3394.91,4428.77 3394.38,4426.38 3392.77,4420.7 3391.9,4417.51 3391.15,4414.15 3390.62,4410.68
  region net GND: 3340,4524.84 3370,4524.84 3370.2,4521.31 3370.73,4517.83 3371.49,4514.47 3372.35,4511.28 3373.97,4505.6 3374.5,4503.21 3374.7,4501.2 3335.3,4501.2 3335.5,4503.21 3336.03,4505.6 3337.65,4511.28 3338.51,4514.47 3339.27,4517.83 3339.8,4521.31
  region net 315_RX: 3464,6128.56 3434,6128.56 3433.8,6132.09 3433.27,6135.56 3432.51,6138.92 3431.65,6142.12 3430.03,6147.8 3429.5,6150.19 3429.3,6152.2 3468.7,6152.2 3468.5,6150.19 3467.97,6147.8 3466.35,6142.12 3465.49,6138.92 3464.73,6135.56 3464.2,6132.09
  region net 315_RX: 3434,5414.84 3464,5414.84 3464.2,5411.31 3464.73,5407.83 3465.49,5404.47 3466.35,5401.28 3467.97,5395.6 3468.5,5393.21 3468.7,5391.2 3429.3,5391.2 3429.5,5393.21 3430.03,5395.6 3431.65,5401.28 3432.51,5404.47 3433.27,5407.83 3433.8,5411.31
  region net +3.3V: 3445.3,6494.62 3415.3,6494.62 3415.06,6497.95 3414.4,6501.28 3413.4,6504.53 3412.17,6507.62 3410.78,6510.45 3409.35,6512.96 3407.95,6515.06 3406.68,6516.67 3453.93,6516.67 3452.66,6515.06 3451.26,6512.96 3449.82,6510.45 3448.44,6507.62 3447.21,6504.53 3446.21,6501.28 3445.55,6497.95
  region net +3.3V: 3368.92,6216.34 3390.31,6195.3 3388.12,6192.77 3386.24,6189.94 3384.65,6186.93 3383.35,6183.87 3382.32,6180.88 3381.57,6178.08 3381.09,6175.6 3380.86,6173.57 3347.27,6206.8 3349.3,6207.05 3351.77,6207.55 3354.55,6208.32 3357.53,6209.35 3360.58,6210.66 3363.57,6212.26 3366.4,6214.15
  region net I2C_SDA: 4037.47,6394.52 4047.47,6394.52 4047.82,6392.71 4048.72,6390.44 4050,6388.12 4051.47,6386.12 4033.47,6386.12 4034.94,6388.12 4036.22,6390.44 4037.13,6392.71
  region net KEY_ENTER: 3961.09,5836.18 3954.02,5829.11 3952.49,5830.15 3950.25,5831.11 3947.7,5831.85 3945.25,5832.22 3957.98,5844.95 3958.35,5842.5 3959.09,5839.95 3960.05,5837.7
  region net KEY_MENU: 3963.09,5887.18 3956.02,5880.11 3954.49,5881.15 3952.25,5882.11 3949.7,5882.85 3947.25,5883.22 3959.98,5895.95 3960.35,5893.5 3961.09,5890.95 3962.05,5888.7
  region net CHG_P: 3957.56,5645.2 3959.06,5635.2 3958.17,5635.1 3957.14,5634.83 3954.83,5633.85 3952.54,5632.47 3950.66,5630.89 3949.16,5648.83 3951.25,5647.5 3953.62,5646.33 3955.85,5645.51
  region net CHG_P: 4137.72,5645.2 4137.72,5635.2 4135.91,5634.85 4133.65,5633.95 4131.32,5632.67 4129.32,5631.2 4129.32,5649.2 4131.32,5647.73 4133.65,5646.45 4135.91,5645.54
  region net CHG_P: 4035.66,5635.2 4035.66,5645.2 4037.47,5645.54 4039.74,5646.45 4042.07,5647.73 4044.06,5649.2 4044.06,5631.2 4042.07,5632.67 4039.74,5633.95 4037.47,5634.85
  region net CHG_P: 4178.02,5635.2 4178.02,5645.2 4179.82,5645.54 4182.09,5646.45 4184.42,5647.73 4186.41,5649.2 4186.41,5631.2 4184.42,5632.67 4182.09,5633.95 4179.82,5634.85
  region net EN: 3388,6373.26 3398,6371.76 3398.31,6370.05 3399.13,6367.81 3400.3,6365.45 3401.63,6363.36 3383.69,6364.86 3385.27,6366.74 3386.65,6369.03 3387.63,6371.34 3387.9,6372.37
  region net EN: 3398,6457.86 3388,6457.86 3387.66,6459.67 3386.75,6461.94 3385.47,6464.26 3384,6466.26 3402,6466.26 3400.53,6464.26 3399.25,6461.94 3398.34,6459.67
  region net VCC: 4625,5740.05 cw(c4625,5830.05) 4535,5830.05 4505,5821.26 cw(c4287.72,5821.26) 4441.36,5667.62 4462.57,5646.41 cw(c4616.21,5492.77) 4616.21,5710.05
